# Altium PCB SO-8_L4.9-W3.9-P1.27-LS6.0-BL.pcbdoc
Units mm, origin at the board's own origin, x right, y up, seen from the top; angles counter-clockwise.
Board outline 18.7 x 19.5 mm, 2 copper layers (Top Layer, Bottom Layer), stack 0 mm thick; 1 components, 0 nets, 8 pads, 0 vias.
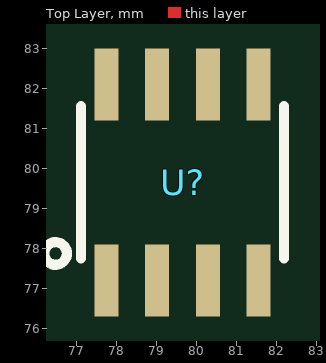
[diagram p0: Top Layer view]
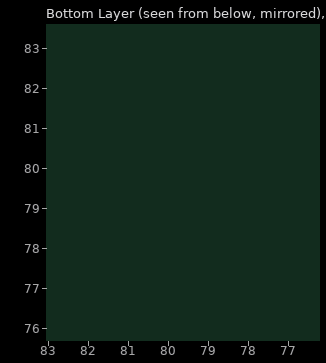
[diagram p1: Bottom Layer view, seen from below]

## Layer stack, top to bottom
Top Layer: signal copper (thickness not stored)
Bottom Layer: signal copper (thickness not stored)

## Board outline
88.549,69.85 69.85,69.85 69.85,89.352 88.549,89.352

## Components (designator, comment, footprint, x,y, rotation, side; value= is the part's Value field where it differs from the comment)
U? "" SO-8_L4.9-W3.9-P1.27-LS6.0-BL 79.659,79.652 r0 top

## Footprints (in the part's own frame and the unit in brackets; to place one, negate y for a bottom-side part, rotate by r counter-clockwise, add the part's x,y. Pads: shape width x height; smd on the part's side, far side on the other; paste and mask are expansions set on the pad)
SO-8_L4.9-W3.9-P1.27-LS6.0-BL [mm]
  rect 0.6x1.8 smd paste+0 mask+0.05: 1(-1.905,-2.45) 2(-0.635,-2.45) 3(0.635,-2.45) 4(1.905,-2.45) 5(1.905,2.45) 6(0.635,2.45) 7(-0.635,2.45) 8(-1.905,2.45)
  silkscreen extent -3.46,-2.06 2.54,1.91

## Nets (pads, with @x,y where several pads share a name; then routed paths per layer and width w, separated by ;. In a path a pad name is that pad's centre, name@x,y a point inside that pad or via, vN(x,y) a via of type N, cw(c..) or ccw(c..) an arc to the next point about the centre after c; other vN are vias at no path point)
pads on no net: U?.1 U?.2 U?.3 U?.4 U?.5 U?.6 U?.7 U?.8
